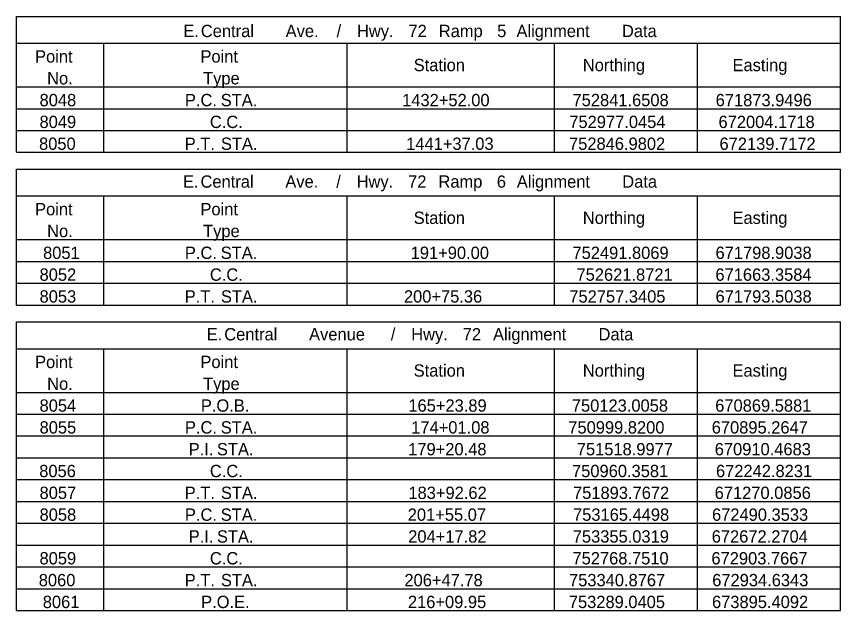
# Model space of a CAD drawing. Extents: x 672566 to 676329, y 739687 to 740710.
# Drawn here: x 674192.9 to 674527.1, y 740175.3 to 740416.3 of the extents above; entities that cross this region are included whole.
import ezdxf

# ---------------------------------------------------------------- set-up
doc = ezdxf.new("R2010")
doc.units = 0
doc.layers.add('S_BASELINE', color=7, linetype='Continuous')

msp = doc.modelspace()

# ---------------------------------------------------------------- linework, layer by layer
at = {"layer": 'S_BASELINE'}
for p, q in [((674192.88, 740416.3), (674527.08, 740416.3)), ((674192.88, 740361.19), (674192.88, 740416.3)), ((674527.08, 740361.19), (674527.08, 740416.3)), ((674192.88, 740405.45), (674527.08, 740405.45)), ((674228.29, 740361.19), (674228.29, 740405.45)), ((674327, 740361.19), (674327, 740405.45)), ((674411.1, 740361.19), (674411.1, 740405.45)), ((674469.09, 740361.19), (674469.09, 740405.45)), ((674192.88, 740387.74), (674527.08, 740387.74)), ((674192.88, 740387.74), (674228.29, 740387.74)), ((674192.88, 740378.89), (674527.08, 740378.89)), ((674192.88, 740370.04), (674527.08, 740370.04)), ((674192.88, 740361.19), (674527.08, 740361.19)), ((674192.88, 740354.33), (674527.08, 740354.33)), ((674192.88, 740299.21), (674192.88, 740354.33)), ((674527.08, 740299.21), (674527.08, 740354.33)), ((674192.88, 740343.48), (674527.08, 740343.48)), ((674228.29, 740299.21), (674228.29, 740343.48)), ((674327, 740299.21), (674327, 740343.48)), ((674411.1, 740299.21), (674411.1, 740343.48)), ((674469.09, 740299.21), (674469.09, 740343.48)), ((674192.88, 740325.77), (674527.08, 740325.77)), ((674192.88, 740325.77), (674228.29, 740325.77)), ((674192.88, 740316.92), (674527.08, 740316.92)), ((674192.88, 740308.07), (674527.08, 740308.07)), ((674192.88, 740299.21), (674527.08, 740299.21)), ((674192.88, 740292.36), (674527.08, 740292.36)), ((674192.88, 740175.27), (674192.88, 740292.36)), ((674527.08, 740175.27), (674527.08, 740292.36)), ((674192.88, 740281.51), (674527.08, 740281.51)), ((674228.29, 740175.27), (674228.29, 740281.51)), ((674327, 740175.27), (674327, 740281.51)), ((674411.1, 740175.27), (674411.1, 740281.51)), ((674469.09, 740175.27), (674469.09, 740281.51)), ((674192.88, 740263.8), (674527.08, 740263.8)), ((674192.88, 740263.8), (674228.29, 740263.8)), ((674192.88, 740254.95), (674527.08, 740254.95)), ((674192.88, 740246.1), (674527.08, 740246.1)), ((674192.88, 740237.24), (674527.08, 740237.24)), ((674192.88, 740228.39), (674527.08, 740228.39)), ((674192.88, 740219.54), (674527.08, 740219.54)), ((674192.88, 740210.68), (674527.08, 740210.68)), ((674192.88, 740201.83), (674527.08, 740201.83)), ((674192.88, 740192.98), (674527.08, 740192.98)), ((674192.88, 740184.13), (674527.08, 740184.13)), ((674192.88, 740175.27), (674527.08, 740175.27))]:
    msp.add_line(p, q, dxfattribs=at)

# ---------------------------------------------------------------- texts
for s, p in [('E.', (674260.53, 740407.93)), (' Central', (674265.8, 740407.93)), (' Ave.', (674300.2, 740407.93)), (' /', (674320.85, 740407.93)), (' Hwy.', (674329.11, 740407.93)), (' 72', (674349.99, 740407.93)), (' Ramp', (674362.3, 740407.93)), (' 5', (674385.97, 740407.93)), (' Alignment', (674393.79, 740407.93)), (' Data', (674436.58, 740407.93)), ('Point', (674200.42, 740397.6)), ('Point', (674267.48, 740397.6)), ('Station', (674353.97, 740394.1)), ('Northing', (674422.56, 740394.1)), ('Easting', (674483.26, 740394.1)), ('No.', (674205.31, 740388.74)), ('Type', (674268.56, 740388.74)), ('8048', (674202.24, 740379.89)), ('P.C.', (674261.19, 740379.89)), (' STA.', (674273.85, 740379.89)), ('1432+52.00', (674349.29, 740379.89)), ('752841.6508', (674418.39, 740379.89)), ('671873.9496', (674476.44, 740379.89)), ('8049', (674202.22, 740371.04)), ('C.C.', (674271.31, 740371.04)), ('752977.0454', (674417.09, 740371.04)), ('672004.1718', (674477.6, 740371.04)), ('8050', (674202.03, 740362.18)), ('P.T.', (674261.11, 740362.18)), (' STA.', (674273.93, 740362.18)), ('1441+37.03', (674350.92, 740362.18)), ('752846.9802', (674416.97, 740362.18)), ('672139.7172', (674477.99, 740362.18)), ('E.', (674260.39, 740346.83)), (' Central', (674265.66, 740346.83)), (' Ave.', (674300.07, 740346.83)), (' /', (674320.71, 740346.83)), (' Hwy.', (674328.97, 740346.83)), (' 72', (674349.85, 740346.83)), (' Ramp', (674362.16, 740346.83)), (' 6', (674385.83, 740346.83)), (' Alignment', (674393.93, 740346.83)), (' Data', (674436.71, 740346.83)), ('Point', (674200.42, 740335.62)), ('Point', (674267.48, 740335.62)), ('Station', (674353.97, 740332.13)), ('Northing', (674422.56, 740332.13)), ('Easting', (674483.26, 740332.13)), ('No.', (674205.31, 740326.77)), ('Type', (674268.56, 740326.77)), ('8051', (674203.66, 740317.92)), ('P.C.', (674261.19, 740317.92)), (' STA.', (674273.85, 740317.92)), ('191+90.00', (674352.75, 740317.92)), ('752491.8069', (674418.37, 740317.92)), ('671798.9038', (674476.38, 740317.92)), ('8052', (674202.24, 740309.07)), ('C.C.', (674271.31, 740309.07)), ('752621.8721', (674420, 740309.07)), ('671663.3584', (674476.34, 740309.07)), ('8053', (674202.24, 740300.21)), ('P.T.', (674261.11, 740300.21)), (' STA.', (674273.93, 740300.21)), ('200+75.36', (674350, 740300.21)), ('752757.3405', (674417.09, 740300.21)), ('671793.5038', (674476.38, 740300.21)), ('E.', (674270.02, 740284.88)), (' Central', (674275.29, 740284.88)), (' Avenue', (674309.7, 740284.88)), (' /', (674342.85, 740284.88)), (' Hwy.', (674351.11, 740284.88)), (' 72', (674371.99, 740284.88)), (' Alignment', (674384.3, 740284.88)), (' Data', (674427.08, 740284.88)), ('Point', (674200.42, 740273.65)), ('Point', (674267.48, 740273.65)), ('Station', (674353.97, 740270.16)), ('Northing', (674422.56, 740270.16)), ('Easting', (674483.26, 740270.16)), ('No.', (674205.31, 740264.8)), ('Type', (674268.56, 740264.8)), ('8054', (674202.24, 740255.95)), ('P.O.B.', (674267.65, 740255.95)), ('165+23.89', (674351.81, 740255.95)), ('750123.0058', (674418.11, 740255.95)), ('670869.5881', (674476.26, 740255.95)), ('8055', (674202.24, 740247.09)), ('P.C.', (674261.19, 740247.09)), (' STA.', (674273.85, 740247.09)), ('174+01.08', (674352.97, 740247.09)), ('750999.8200', (674416.68, 740247.09)), ('670895.2647', (674474.84, 740247.09)), ('P.I.', (674262.72, 740238.24)), (' STA.', (674272.31, 740238.24)), ('179+20.48', (674351.75, 740238.24)), ('751518.9977', (674420.12, 740238.24)), ('670910.4683', (674476.06, 740238.24)), ('8056', (674202.11, 740229.39)), ('C.C.', (674271.31, 740229.39)), ('750960.3581', (674418.19, 740229.39)), ('672242.8231', (674476.57, 740229.39)), ('8057', (674202.24, 740220.54)), ('P.T.', (674261.11, 740220.54)), (' STA.', (674273.93, 740220.54)), ('183+92.62', (674351.83, 740220.54)), ('751893.7672', (674418.59, 740220.54)), ('671270.0856', (674476.04, 740220.54)), ('8058', (674202.24, 740211.68)), ('P.C.', (674261.19, 740211.68)), (' STA.', (674273.85, 740211.68)), ('201+55.07', (674351.55, 740211.68)), ('753165.4498', (674418.59, 740211.68)), ('672490.3533', (674474.96, 740211.68)), (' STA.', (674272.31, 740202.83)), ('204+17.82', (674351.75, 740202.83)), ('753355.0319', (674418.49, 740202.83)), ('672672.2704', (674474.84, 740202.83)), ('P.I.', (674262.72, 740202.83)), ('8059', (674202.22, 740193.98)), ('C.C.', (674271.31, 740193.98)), ('752768.7510', (674418.37, 740193.98)), ('672903.7667', (674474.72, 740193.98)), ('8060', (674201.91, 740185.12)), ('P.T.', (674261.11, 740185.12)), (' STA.', (674273.93, 740185.12)), ('206+47.78', (674350.21, 740185.12)), ('753340.8767', (674416.97, 740185.12)), ('672934.6343', (674475.04, 740185.12)), ('8061', (674203.54, 740176.27)), ('P.O.E.', (674267.77, 740176.27)), ('216+09.95', (674351.63, 740176.27)), ('753289.0405', (674416.89, 740176.27)), ('673895.4092', (674474.96, 740176.27))]:
    msp.add_text(s, height=4.994, dxfattribs=at).set_placement(p)

doc.saveas('drawing.dxf')
